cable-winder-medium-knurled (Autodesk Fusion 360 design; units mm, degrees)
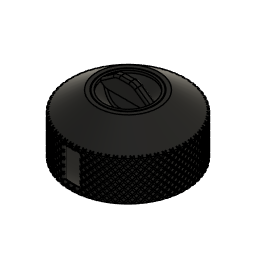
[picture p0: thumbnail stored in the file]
parameter "radius" = 30
parameter "height" = 40
parameter "gap" = 0.35
sketch "Skizze" plane through (0, 0, 0) normal (0, 1, 0) x axis (1, 0, 0)
  line L1 (30, 0) -> (0, 0)
  line L2 (30, -10.1971) -> (30, 0)
  line L3 (16, -20) -> (30, -10.1971)
  line L4 (14, -20) -> (16, -20)
  line L5 (28, -9.156) -> (28, 0)
  line L6 (14, -18.9589) -> (28, -9.156)
  line L7 (14, -18.9589) -> (14, -20)
  line L8 (12.45, -20) -> (13.65, -20)
  line L9 (13.65, -18.7767) -> (13.65, -20)
  line L10 (15.6652, -17.3656) -> (13.65, -18.7767)
  line L11 (8, -11.9984) -> (15.6652, -17.3656)
  line L12 (8, 0) -> (8, -11.9984)
  line L13 (12.45, -18.7767) -> (12.45, -20)
  line L14 (5.626, -13.9984) -> (12.45, -18.7767)
  line L15 (0, -13.9984) -> (5.626, -13.9984)
  line L16 (12.45, -18.7767) -> (13.65, -18.7767)
  line L17 (0, 0) -> (0, -13.9984)
  line L18 (0, -20) -> (0, -13.9984)
  line L19 (12.45, -20) -> (0, -20)
  line L20 (0, -11.9984) -> (8, -11.9984)
  line L21 (15.3795, -17.1656) -> (15.3795, -17.5656)
  line L22 (0, 0) -> (0, 13.9984)
  line L23 (0, 11.9984) -> (8, 11.9984)
  line L24 (8, 0) -> (8, 11.9984)
  line L25 (8, 11.9984) -> (15.6652, 17.3656)
  line L26 (12.45, 20) -> (13.65, 20)
  line L27 (0, 20) -> (0, 13.9984)
  line L28 (12.45, 20) -> (0, 20)
  line L29 (13.65, 18.7767) -> (13.65, 20)
  line L30 (15.6652, 17.3656) -> (13.65, 18.7767)
  line L31 (14, 18.9589) -> (14, 20)
  line L32 (14, 20) -> (16, 20)
  line L33 (16, 20) -> (30, 10.1971)
  line L34 (14, 18.9589) -> (28, 9.156)
  line L35 (28, 9.156) -> (28, 0)
  line L36 (30, 10.1971) -> (30, 0)
  line L37 (-2, -13.9984) -> (2, -13.9984)
  line L38 (4.4501, -25.6016) -> (12.45, -20)
  line L39 (0, -25.6016) -> (4.4501, -25.6016)
  line L40 (12.45, 18.7767) -> (12.45, 20)
  line L41 (5.626, 13.9984) -> (12.45, 18.7767)
  line L42 (0, 13.9984) -> (5.626, 13.9984)
  line L43 (-4.4501, -25.6016) -> (-12.45, -20)
  line L44 (0, -25.6016) -> (-4.4501, -25.6016)
  line L45 (-5.626, -13.9984) -> (-12.45, -18.7767)
  line L46 (-12.45, -18.7767) -> (-12.45, -20)
  line L47 (0, -13.9984) -> (-5.626, -13.9984)
  line L48 (0, 13.9984) -> (-5.626, 13.9984)
  line L49 (-5.626, 13.9984) -> (-12.45, 18.7767)
  line L50 (-12.45, 18.7767) -> (-12.45, 20)
  line L51 (-12.45, 20) -> (0, 20)
  line L52 (4, -8) -> (-4, -8)
  line L53 (4, 8) -> (4, -8)
  line L54 (-4, 8) -> (4, 8)
  line L55 (-4, -8) -> (-4, 8)
  line L56 (4, 8) -> (-4, -8)
  line L57 (-4, 8) -> (4, -8)
  point P1 (0, 0)
  point P2 (0, 0)
  point P6 (28, 0)
  point P14 (8, 0)
  point P19 (0, 0)
  point P21 (0, -11.9984)
  point P22 (15.3795, -17.5656)
  point P23 (15.3795, -17.1656)
  point P26 (0, 0)
  point P30 (0, 0)
  point P3 (30, 0)
  point P43 (30, 0)
  point P4 (30, -10.1971)
  point P40 (30, 10.1971)
  point P5 (16, -20)
  point P39 (16, 20)
  point P42 (28, 0)
  point P7 (28, -9.156)
  point P41 (28, 9.156)
  point P8 (14, -20)
  point P37 (14, 20)
  point P9 (14, -18.9589)
  point P38 (14, 18.9589)
  point P10 (13.65, -20)
  point P33 (13.65, 20)
  point P11 (13.65, -18.7767)
  point P36 (13.65, 18.7767)
  point P12 (15.6652, -17.3656)
  point P32 (15.6652, 17.3656)
  point P13 (8, -11.9984)
  point P25 (8, 11.9984)
  point P31 (8, 0)
  point P15 (12.45, -20)
  point P34 (12.45, 20)
  point P17 (5.626, -13.9984)
  point P29 (5.626, 13.9984)
  point P18 (0, -13.9984)
  point P24 (0, 13.9984)
  point P28 (0, 0)
  point P20 (0, -20)
  point P35 (0, 20)
  point P27 (0, 11.9984)
  point P46 (0, -20)
  point P49 (12.45, 20)
  point P16 (12.45, -18.7767)
  point P50 (12.45, 18.7767)
  point P51 (5.626, 13.9984)
  point P52 (0, 13.9984)
  point P53 (-12.45, -20)
  point P56 (-12.45, -18.7767)
  point P57 (-5.626, -13.9984)
  point P58 (0, -13.9984)
  point P47 (4.4501, -25.6016)
  point P54 (-4.4501, -25.6016)
  point P48 (0, -25.6016)
  point P55 (0, -25.6016)
  point P64 (-12.45, 20)
  point P63 (0, 20)
  point P62 (-12.45, 20)
  point P61 (-12.45, 18.7767)
  point P59 (-5.626, 13.9984)
  point P60 (0, 13.9984)
  point P69 (0, 0)
  point P70 (21.3189, -16.2757)
  point P67 (4, 8)
  point P68 (-4, 8)
  point P66 (4, -8)
  coincident P1 P2
  horizontal L1
  perpendicular L1 L2
  perpendicular L2 L4
  coincident L1 P6
  perpendicular L1 L5
  parallel L3 L6
  perpendicular L4 L7
  perpendicular L7 L8
  perpendicular L8 L9
  parallel L6 L10
  coincident L1 P14
  perpendicular L1 L12
  perpendicular L8 L13
  parallel L11 L14
  horizontal L16
  collinear L4 L8
  coincident P1 P19
  perpendicular L1 L17
  perpendicular L8 L18
  perpendicular L13 L19
  coincident L17 P21
  perpendicular L17 L20
  coincident L10 P22
  coincident L11 P23
  vertical L21
  symmetric P1 L1 P26
  symmetric P2 L1 P30
  symmetric P3 L1 P43
  symmetric L1 P4 P40
  symmetric L1 P5 P39
  symmetric L1 P6 P42
  symmetric L1 P7 P41
  symmetric L1 P8 P37
  symmetric L1 P9 P38
  symmetric L1 P10 P33
  symmetric L1 P11 P36
  symmetric L1 P12 P32
  symmetric L1 P13 P25
  symmetric L1 P14 P31
  symmetric L1 P15 P34
  symmetric L1 P17 P29
  symmetric L1 P18 P24
  symmetric L1 P19 P28
  symmetric L1 P20 P35
  symmetric L1 P21 P27
  horizontal L37
  coincident P20 P46
  collinear L15 L37
  perpendicular L18 L39
  symmetric L1 P15 P49
  symmetric L1 P16 P50
  symmetric L1 P17 P51
  symmetric L1 P18 P52
  symmetric P15 L18 P53
  symmetric P16 L18 P56
  symmetric P17 L18 P57
  symmetric P18 L18 P58
  symmetric L18 P47 P54
  symmetric L18 P48 P55
  symmetric P34 L27 P64
  symmetric P35 L27 P63
  symmetric L27 P49 P62
  symmetric L27 P50 P61
  symmetric L27 P51 P59
  symmetric L27 P52 P60
  horizontal L52
  perpendicular L52 L53
  parallel L52 L54
  parallel L53 L55
  coincident L56 P69
  coincident L57 P69
  coincident P30 P69
  coincident L3 P70
  dimension "d43" distance P2 P3 = 30 (= "radius")
  dimension "d45" angle L2 L3 = 125
  dimension "d47" distance L3 L6 = 2
  dimension "d48" distance L2 L5 = 2
  dimension "d49" distance P5 L7 = 2
  dimension "d50" distance L7 L9 = 0.35 (= "gap")
  dimension "d51" distance L6 L10 = 0.35 (= "d50")
  dimension "d52" angle L1 L11 = 35
  dimension "d54" distance L11 L14 = 3
  dimension "d55" distance P10 P15 = 1.2
  dimension "d57" distance P5 P18 = 16
  dimension "d58" distance L1 L19 = 20 (= "height / 2")
  dimension "d59" distance L15 L20 = 2
  dimension "d60" distance P22 P23 = 0.4
  dimension "d61" distance L12 L17 = 8
  dimension "d69" angle L19 L38 = 35
  dimension "d70" distance L19 L39 = 5.6016 (= "d71 - 0.4 mm")
  dimension "d71" distance L15 L19 = 6.0016
  dimension "d84" distance P67 P68 = 8
  dimension "d85" distance P66 P67 = 16
revolve "Drehen1" sketch "Skizze" AlongAngle 360 bodies "Core"
revolve "Drehen1" sketch "Skizze" AlongAngle 360 bodies "Ring"
ground "Fixieren"
joint "Zusammenfügen" alignAngle 0 alignOffsetX 0 alignOffsetY 0 alignOffsetZ 0
chamfer "Fase1" distance 3 Rotate Angle 45
extrude "Extrusion3" cut sketch "Skizze" profile of L27 L28 L40 L41 L42 L48 L49 L50 L51 distance 4
extrude "Extrusion4" add sketch "Skizze" profile of L13 L14 L15 L18 L19 L37 L38 L39 L43 L44 L45 L46 L47 distance 4
chamfer "Fase2" distance 3 Rotate Angle 45
fillet "Abrundung1" radius 1 6
fillet "Abrundung2" radius 4
fillet "Abrundung5" radius 20
extrude "Extrusion5" cut sketch "Skizze" profile of L1 L17 L20 L22 L23 L52 L53 L54 L55 no distance stored
fillet "Abrundung3" radius 1 1
fillet "Abrundung1" radius 1 1
fillet "Abrundung4" radius 1
fillet "Abrundung2" radius 0.6
coil_primitive "Grundkörper Spirale" Diameter 60 (= "2 * radius") SectionSize 1 TaperAngle 0 Revolutions 0.2
circular_pattern "C-Anordnung" countU 60 (= "2 * radius / 1 mm") TotalAngle 360
mirror "Spiegeln" mirrorStitchTolerance 0.1
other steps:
extrude "Extrusion1" cut sketch "Skizze" profile of L1 L17 L20 L22 L23 L52 L53 L54 L55 no distance stored
create_component "Komponente erstellen1"
create_component "Komponente erstellen2"
joint_origin "Gelenkursprung1"
joint_origin "Gelenkursprung1"
named bodies: "Core", "Ring"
